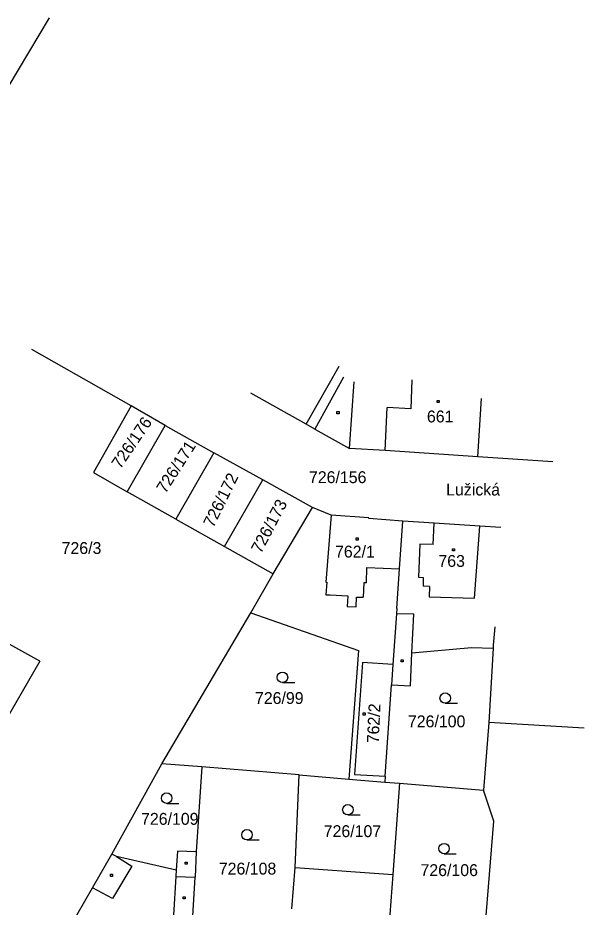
# Model space of a CAD drawing. Extents: x -711879 to -711361, y -1048782 to -1048177.
# Drawn here: x -711487 to -711406, y -1048304.3 to -1048177.1 of the extents above; entities that cross this region are included whole.
import ezdxf

# ---------------------------------------------------------------- set-up
doc = ezdxf.new("R2010")
doc.units = 0
for name, color, linetype in [('Vrstva 1', 7, 'Continuous'), ('Vrstva 14', 7, 'Continuous'), ('Vrstva 15', 7, 'Continuous'), ('Vrstva 2', 7, 'Continuous'), ('Vrstva 23', 7, 'Continuous'), ('Vrstva 25', 7, 'Continuous'), ('Vrstva 38', 7, 'Continuous'), ('Vrstva 46', 7, 'Continuous')]:
    doc.layers.add(name, color=color, linetype=linetype)

msp = doc.modelspace()

# ---------------------------------------------------------------- linework, layer by layer
at = {"layer": 'Vrstva 1'}
for p, q in [((-711482.5, -1048177.05), (-711529.35, -1048255.3)), ((-711470.77, -1048232.61), (-711484.99, -1048224.54)), ((-711439.55, -1048238.7), (-711438.87, -1048229.13)), ((-711430.63, -1048228.87), (-711430.79, -1048233.02)), ((-711445.77, -1048235.19), (-711453.65, -1048230.76)), ((-711421.23, -1048239.89), (-711420.7, -1048231.56)), ((-711470.77, -1048232.61), (-711476.16, -1048242.11)), ((-711465.9, -1048235.38), (-711470.77, -1048232.61)), ((-711434.45, -1048238.98), (-711434.16, -1048232.84)), ((-711430.79, -1048233.02), (-711434.16, -1048232.84)), ((-711471.37, -1048244.89), (-711465.9, -1048235.38)), ((-711465.9, -1048235.38), (-711458.95, -1048239.3)), ((-711444.5, -1048235.91), (-711445.77, -1048235.19)), ((-711444.5, -1048235.91), (-711439.55, -1048238.7)), ((-711458.95, -1048239.3), (-711464.4, -1048248.8)), ((-711451.96, -1048243.18), (-711458.95, -1048239.3)), ((-711434.45, -1048238.98), (-711439.55, -1048238.7)), ((-711421.23, -1048239.89), (-711434.45, -1048238.98)), ((-711410.49, -1048240.58), (-711421.23, -1048239.89)), ((-711476.16, -1048242.11), (-711471.37, -1048244.89)), ((-711457.43, -1048252.72), (-711451.96, -1048243.18)), ((-711444.87, -1048247.13), (-711451.96, -1048243.18)), ((-711464.4, -1048248.8), (-711471.37, -1048244.89)), ((-711450.47, -1048256.62), (-711444.87, -1048247.13)), ((-711442.16, -1048248.24), (-711444.87, -1048247.13)), ((-711464.4, -1048248.8), (-711457.43, -1048252.72)), ((-711436.78, -1048248.61), (-711442.16, -1048248.24)), ((-711436.79, -1048248.73), (-711436.78, -1048248.61)), ((-711431.93, -1048249.1), (-711436.79, -1048248.73)), ((-711432.41, -1048255.91), (-711431.93, -1048249.1)), ((-711427.47, -1048249.4), (-711431.93, -1048249.1)), ((-711420.92, -1048249.81), (-711427.47, -1048249.4)), ((-711417.93, -1048250.01), (-711420.92, -1048249.81)), ((-711457.43, -1048252.72), (-711450.47, -1048256.62)), ((-711432.81, -1048261.58), (-711432.41, -1048255.91)), ((-711453.67, -1048262.2), (-711450.47, -1048256.62)), ((-711432.81, -1048261.58), (-711432.86, -1048262.34)), ((-711466.4, -1048283.81), (-711453.67, -1048262.2)), ((-711453.67, -1048262.2), (-711438.26, -1048267.59)), ((-711432.86, -1048262.34), (-711433.36, -1048269.6)), ((-711418.79, -1048264.2), (-711419.02, -1048266.82)), ((-711483.84, -1048269.13), (-711489.42, -1048266.01)), ((-711438.26, -1048267.59), (-711439.67, -1048286.01)), ((-711430.83, -1048272.64), (-711430.63, -1048267.93)), ((-711430.63, -1048267.93), (-711422.13, -1048267.19)), ((-711422.13, -1048267.19), (-711419.04, -1048267.27)), ((-711419.04, -1048267.27), (-711419.63, -1048277.89)), ((-711419.02, -1048266.82), (-711419.04, -1048267.27)), ((-711483.84, -1048269.13), (-711489.64, -1048279.13)), ((-711437.68, -1048269.3), (-711438.84, -1048285.34)), ((-711433.36, -1048269.6), (-711437.68, -1048269.3)), ((-711433.36, -1048269.6), (-711433.56, -1048272.5)), ((-711434.47, -1048285.6), (-711433.56, -1048272.5)), ((-711433.56, -1048272.5), (-711430.83, -1048272.64)), ((-711419.63, -1048277.89), (-711420.4, -1048287.59)), ((-711406, -1048278.71), (-711419.63, -1048277.89)), ((-711473.55, -1048296.74), (-711466.4, -1048283.81)), ((-711460.69, -1048284.25), (-711466.4, -1048283.81)), ((-711460.69, -1048284.25), (-711461.49, -1048296.41)), ((-711446.78, -1048285.42), (-711460.69, -1048284.25)), ((-711447.35, -1048298.64), (-711446.78, -1048285.42)), ((-711446.78, -1048285.42), (-711439.67, -1048286.01)), ((-711438.84, -1048285.34), (-711434.47, -1048285.6)), ((-711434.47, -1048285.6), (-711434.53, -1048286.43)), ((-711439.67, -1048286.01), (-711434.53, -1048286.43)), ((-711434.53, -1048286.43), (-711432.43, -1048286.6)), ((-711432.43, -1048286.6), (-711433.37, -1048299.67)), ((-711432.43, -1048286.6), (-711420.4, -1048287.59)), ((-711418.94, -1048292.02), (-711420.4, -1048287.59)), ((-711420.3, -1048309.21), (-711418.94, -1048292.02)), ((-711476.33, -1048301.57), (-711473.55, -1048296.74)), ((-711472.87, -1048297.11), (-711473.55, -1048296.74)), ((-711464.36, -1048299.03), (-711472.87, -1048297.11)), ((-711464.15, -1048296.3), (-711464.36, -1048299.03)), ((-711461.49, -1048296.41), (-711464.15, -1048296.3)), ((-711461.49, -1048296.41), (-711461.63, -1048300.05)), ((-711447.83, -1048304.56), (-711447.35, -1048298.64)), ((-711447.35, -1048298.64), (-711433.37, -1048299.67)), ((-711433.37, -1048299.67), (-711433.96, -1048307.71)), ((-711461.96, -1048305.62), (-711461.63, -1048300.05)), ((-711481.7, -1048310.92), (-711476.33, -1048301.57))]:
    msp.add_line(p, q, dxfattribs=at)
at = {"layer": 'Vrstva 2'}
for p, q in [((-711445.77, -1048235.19), (-711441.04, -1048226.92)), ((-711440.43, -1048228.47), (-711444.5, -1048235.91)), ((-711442.16, -1048248.24), (-711442.96, -1048257.81)), ((-711427.62, -1048252.43), (-711427.47, -1048249.4)), ((-711421.7, -1048260.11), (-711420.92, -1048249.81)), ((-711429.48, -1048252.39), (-711429.7, -1048257.1)), ((-711427.62, -1048252.43), (-711429.48, -1048252.39)), ((-711437.14, -1048257.93), (-711437.08, -1048255.74)), ((-711437.08, -1048255.74), (-711432.41, -1048255.91)), ((-711429.7, -1048257.1), (-711429.04, -1048257.14)), ((-711429.04, -1048257.14), (-711429.05, -1048258.42)), ((-711442.96, -1048257.81), (-711442.78, -1048257.81)), ((-711442.78, -1048257.81), (-711442.95, -1048259.62)), ((-711437.52, -1048257.92), (-711437.6, -1048259.98)), ((-711437.14, -1048257.93), (-711437.52, -1048257.92)), ((-711428.14, -1048258.43), (-711429.05, -1048258.42)), ((-711428.14, -1048258.43), (-711428.18, -1048259.93)), ((-711442.95, -1048259.62), (-711442.32, -1048259.65)), ((-711442.32, -1048259.65), (-711439.82, -1048259.79)), ((-711439.82, -1048259.79), (-711439.88, -1048261.32)), ((-711438.6, -1048261.36), (-711438.55, -1048259.95)), ((-711438.55, -1048259.95), (-711437.6, -1048259.98)), ((-711428.18, -1048259.93), (-711421.7, -1048260.11)), ((-711439.88, -1048261.32), (-711438.6, -1048261.36)), ((-711430.38, -1048262.42), (-711432.86, -1048262.34)), ((-711430.63, -1048267.93), (-711430.38, -1048262.42)), ((-711472.87, -1048297.11), (-711470.67, -1048298.48)), ((-711470.67, -1048298.48), (-711473.45, -1048303.12)), ((-711464.36, -1048299.03), (-711464.41, -1048299.95)), ((-711464.41, -1048299.95), (-711464.73, -1048305.49)), ((-711464.41, -1048299.95), (-711461.63, -1048300.05)), ((-711473.45, -1048303.12), (-711476.33, -1048301.57))]:
    msp.add_line(p, q, dxfattribs=at)
at = {"layer": 'Vrstva 23'}
for p, q in [((-711449.15, -1048272.2), (-711447.4, -1048272.2)), ((-711425.87, -1048275.16), (-711424.12, -1048275.16)), ((-711465.7, -1048289.48), (-711463.95, -1048289.48)), ((-711439.79, -1048291.14), (-711438.04, -1048291.14)), ((-711454.22, -1048294.72), (-711452.47, -1048294.72)), ((-711426.04, -1048296.71), (-711424.29, -1048296.71))]:
    msp.add_line(p, q, dxfattribs=at)
for centre in [(-711449.15, -1048271.45), (-711425.87, -1048274.41), (-711465.7, -1048288.73), (-711439.79, -1048290.39), (-711454.22, -1048293.97), (-711426.04, -1048295.96)]:
    msp.add_circle(centre, 0.75, dxfattribs=at)
at = {"layer": 'Vrstva 25'}
for p, q in [((-711427.03, -1048231.82), (-711426.73, -1048231.82)), ((-711427.03, -1048232.12), (-711427.03, -1048231.82)), ((-711426.73, -1048232.12), (-711427.03, -1048232.12)), ((-711426.73, -1048231.82), (-711426.73, -1048232.12)), ((-711441.36, -1048233.41), (-711441.06, -1048233.41)), ((-711441.36, -1048233.71), (-711441.36, -1048233.41)), ((-711441.06, -1048233.41), (-711441.06, -1048233.71)), ((-711441.06, -1048233.71), (-711441.36, -1048233.71)), ((-711438.63, -1048251.49), (-711438.33, -1048251.49)), ((-711438.63, -1048251.79), (-711438.63, -1048251.49)), ((-711438.33, -1048251.79), (-711438.63, -1048251.79)), ((-711438.33, -1048251.49), (-711438.33, -1048251.79)), ((-711424.85, -1048253.05), (-711424.55, -1048253.05)), ((-711424.85, -1048253.35), (-711424.85, -1048253.05)), ((-711424.55, -1048253.35), (-711424.85, -1048253.35)), ((-711424.55, -1048253.05), (-711424.55, -1048253.35)), ((-711432.17, -1048268.94), (-711431.87, -1048268.94)), ((-711432.17, -1048269.24), (-711432.17, -1048268.94)), ((-711431.87, -1048268.94), (-711431.87, -1048269.24)), ((-711431.87, -1048269.24), (-711432.17, -1048269.24)), ((-711437.63, -1048276.54), (-711437.33, -1048276.54)), ((-711437.63, -1048276.84), (-711437.63, -1048276.54)), ((-711437.33, -1048276.84), (-711437.63, -1048276.84)), ((-711437.33, -1048276.54), (-711437.33, -1048276.84)), ((-711463.06, -1048297.9), (-711462.76, -1048297.9)), ((-711463.06, -1048298.2), (-711463.06, -1048297.9)), ((-711462.76, -1048298.2), (-711463.06, -1048298.2)), ((-711462.76, -1048297.9), (-711462.76, -1048298.2)), ((-711473.73, -1048299.63), (-711473.43, -1048299.63)), ((-711473.73, -1048299.93), (-711473.73, -1048299.63)), ((-711473.43, -1048299.63), (-711473.43, -1048299.93)), ((-711473.43, -1048299.93), (-711473.73, -1048299.93)), ((-711463.34, -1048302.85), (-711463.04, -1048302.85)), ((-711463.34, -1048303.15), (-711463.34, -1048302.85)), ((-711463.04, -1048303.15), (-711463.34, -1048303.15)), ((-711463.04, -1048302.85), (-711463.04, -1048303.15))]:
    msp.add_line(p, q, dxfattribs=at)
at = {"layer": 'Vrstva 46'}
for p, q in [((-711470.77, -1048232.61), (-711470.77, -1048232.61)), ((-711434.16, -1048232.84), (-711434.16, -1048232.84)), ((-711465.9, -1048235.38), (-711465.9, -1048235.38)), ((-711445.77, -1048235.19), (-711445.77, -1048235.19)), ((-711444.5, -1048235.91), (-711444.5, -1048235.91)), ((-711458.95, -1048239.3), (-711458.95, -1048239.3)), ((-711439.55, -1048238.7), (-711439.55, -1048238.7)), ((-711451.96, -1048243.18), (-711451.96, -1048243.18)), ((-711444.87, -1048247.13), (-711444.87, -1048247.13)), ((-711442.16, -1048248.24), (-711442.16, -1048248.24)), ((-711436.79, -1048248.73), (-711436.79, -1048248.73)), ((-711436.78, -1048248.61), (-711436.78, -1048248.61)), ((-711431.93, -1048249.1), (-711431.93, -1048249.1)), ((-711427.47, -1048249.4), (-711427.47, -1048249.4)), ((-711420.92, -1048249.81), (-711420.92, -1048249.81)), ((-711450.47, -1048256.62), (-711450.47, -1048256.62)), ((-711432.81, -1048261.58), (-711432.81, -1048261.58)), ((-711432.86, -1048262.34), (-711432.86, -1048262.34)), ((-711419.02, -1048266.82), (-711419.02, -1048266.82)), ((-711483.84, -1048269.13), (-711483.84, -1048269.13)), ((-711433.36, -1048269.6), (-711433.36, -1048269.6)), ((-711433.56, -1048272.5), (-711433.56, -1048272.5)), ((-711419.63, -1048277.89), (-711419.63, -1048277.89)), ((-711466.4, -1048283.81), (-711466.4, -1048283.81)), ((-711460.69, -1048284.25), (-711460.69, -1048284.25)), ((-711446.78, -1048285.42), (-711446.78, -1048285.42)), ((-711434.47, -1048285.6), (-711434.47, -1048285.6)), ((-711439.67, -1048286.01), (-711439.67, -1048286.01)), ((-711434.53, -1048286.43), (-711434.53, -1048286.43)), ((-711420.4, -1048287.59), (-711420.4, -1048287.59))]:
    msp.add_line(p, q, dxfattribs=at)

# ---------------------------------------------------------------- texts
at = {"layer": 'Vrstva 14'}
for s, rotation, p in [('726/176', 55.85157, (-711472.32, -1048241.73)), ('726/171', 57.47337, (-711465.87, -1048245.23)), ('726/172', 63.70632, (-711459.04, -1048250.12)), ('726/173', 62.34912, (-711452.22, -1048253.83))]:
    msp.add_text(s, height=1.7, rotation=rotation, dxfattribs=at).set_placement(p)
for s, p in [('726/156', (-711445.356, -1048243.65)), ('726/3', (-711480.73, -1048253.79)), ('726/99', (-711453.08, -1048275.26)), ('726/100', (-711431.208, -1048278.6)), ('726/109', (-711469.37, -1048292.55)), ('726/107', (-711443.25, -1048294.31)), ('726/108', (-711458.25, -1048299.67)), ('726/106', (-711429.41, -1048299.89))]:
    msp.add_text(s, height=1.7, dxfattribs=at).set_placement(p)
at = {"layer": 'Vrstva 15'}
for s, p in [('661', (-711428.49, -1048234.96)), ('762/1', (-711441.63, -1048254.3)), ('763', (-711426.85, -1048255.64))]:
    msp.add_text(s, height=1.7, dxfattribs=at).set_placement(p)
msp.add_text('762/2', height=1.7, rotation=87.34581, dxfattribs=at).set_placement((-711435.383, -1048280.912))
at = {"layer": 'Vrstva 38'}
msp.add_text('Lužická', height=1.7, dxfattribs=at).set_placement((-711425.74, -1048245.42))

doc.saveas('drawing.dxf')
